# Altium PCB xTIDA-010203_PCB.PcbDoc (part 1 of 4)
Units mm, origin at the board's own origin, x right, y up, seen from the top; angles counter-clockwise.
Board outline 200 x 130 mm, 4 copper layers (Top Layer, Signal Layer 1, Signal Layer 2, Bottom Layer), stack 1.588 mm thick; 249 components, 140 nets, 768 pads, 520 vias.
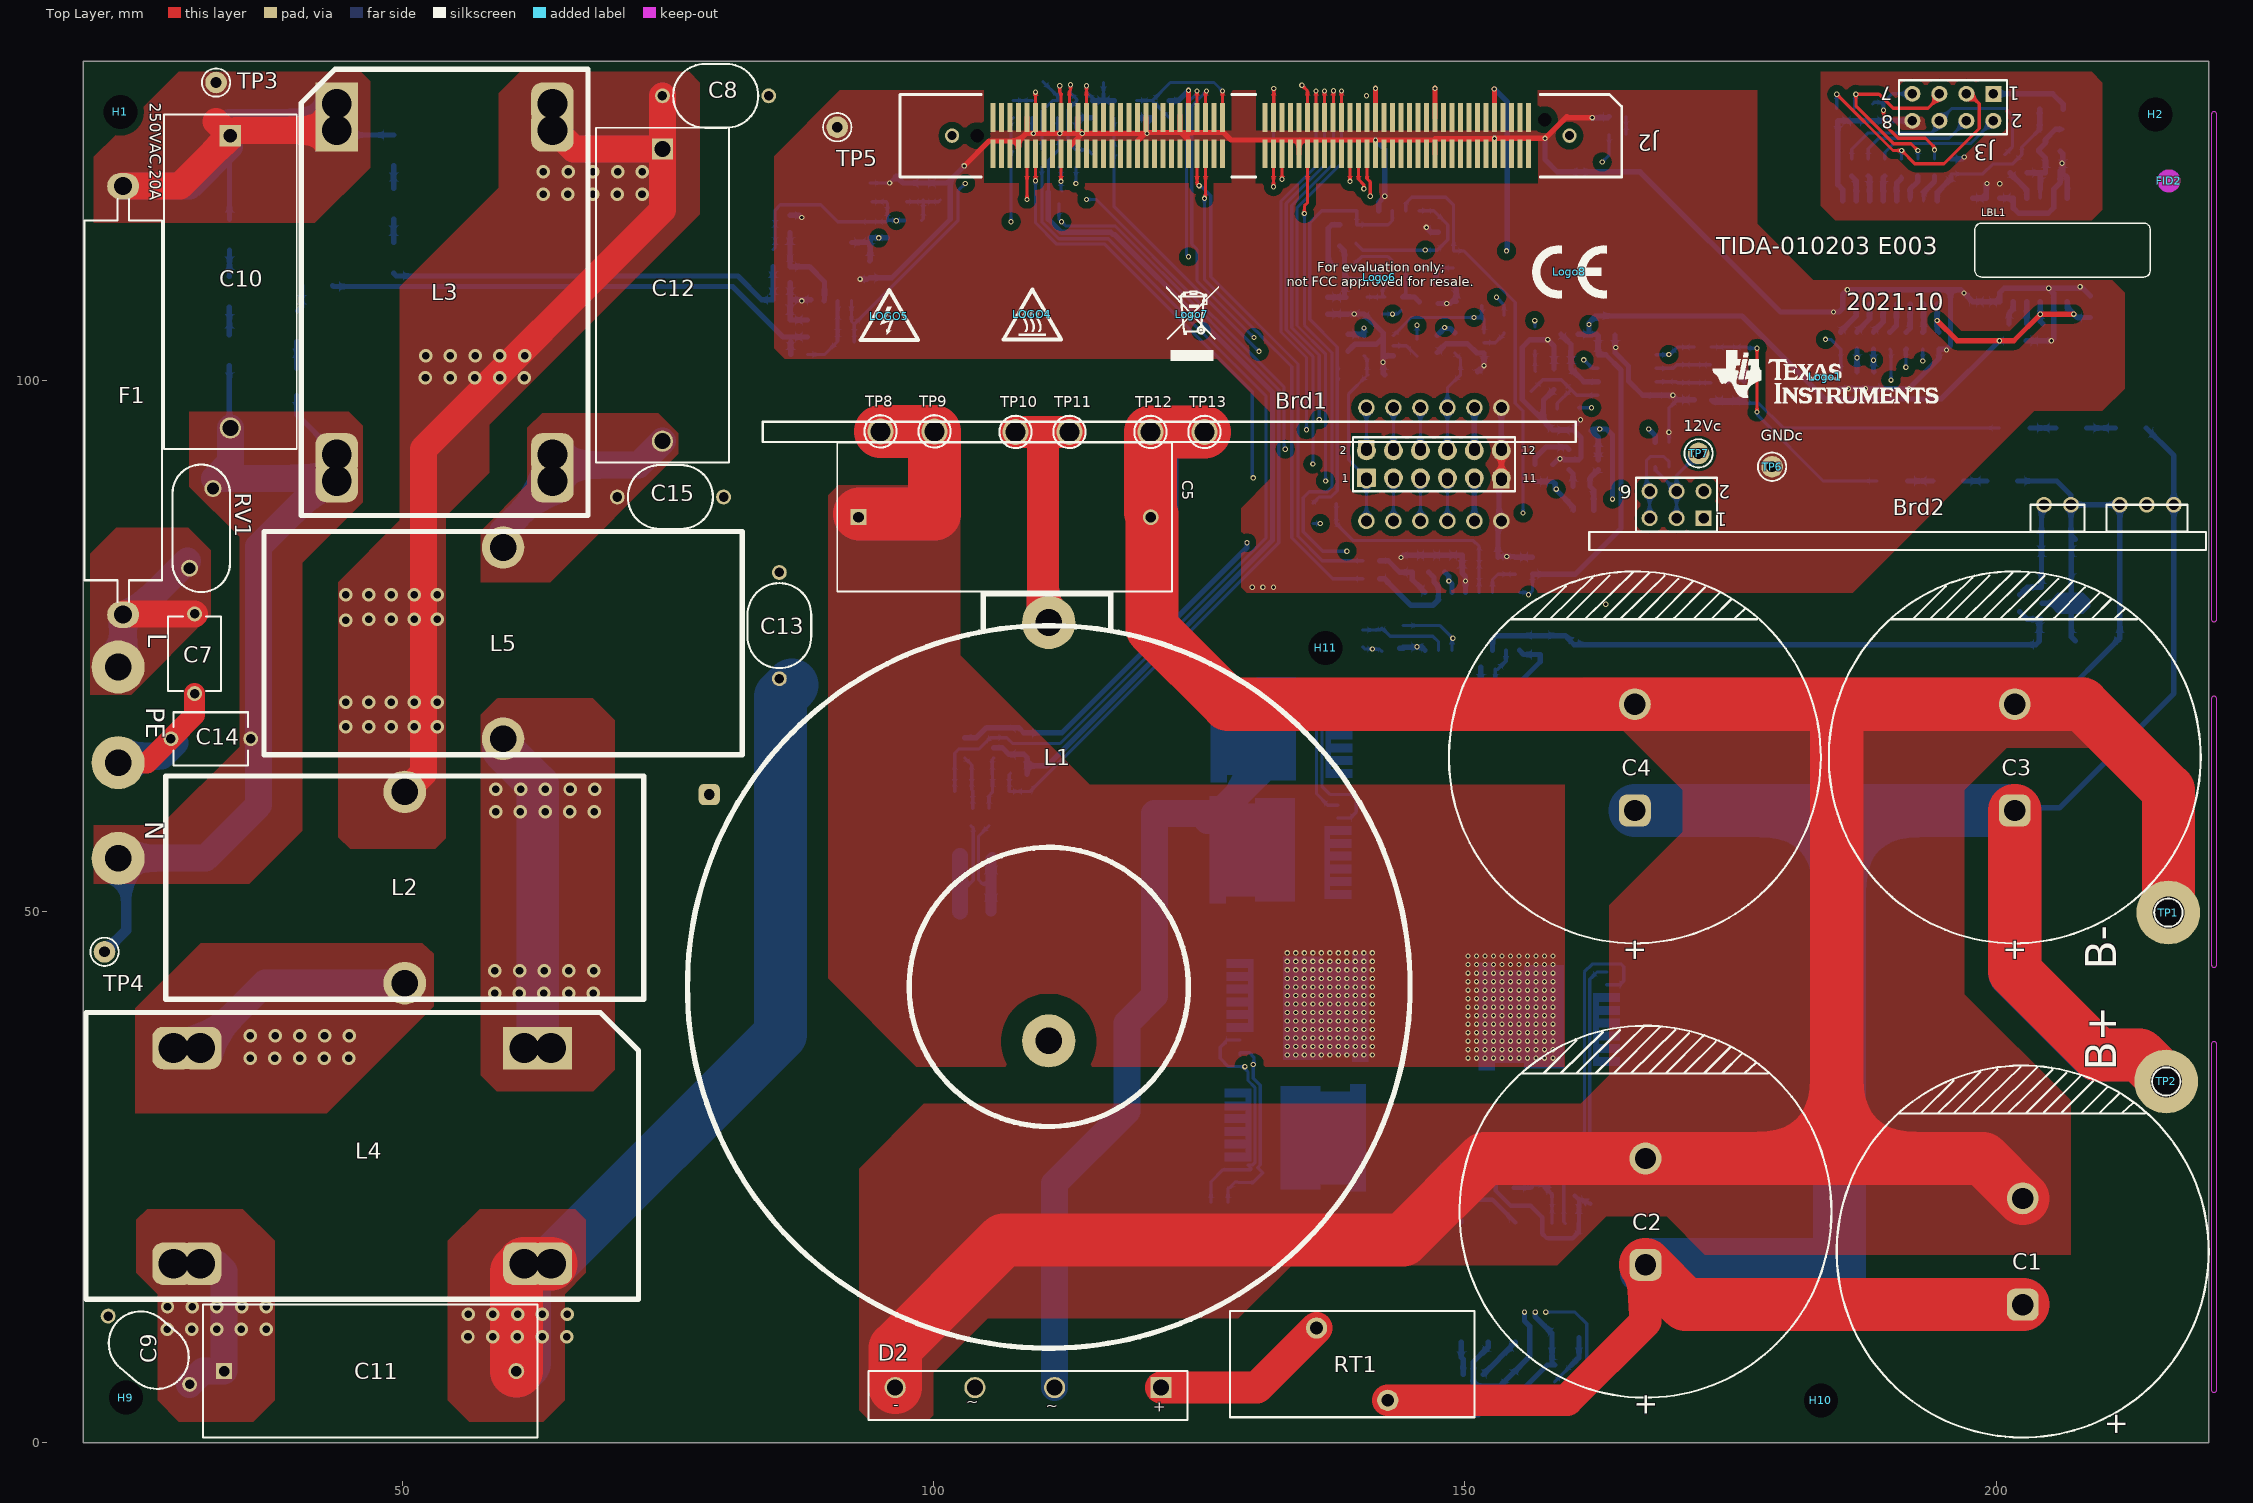
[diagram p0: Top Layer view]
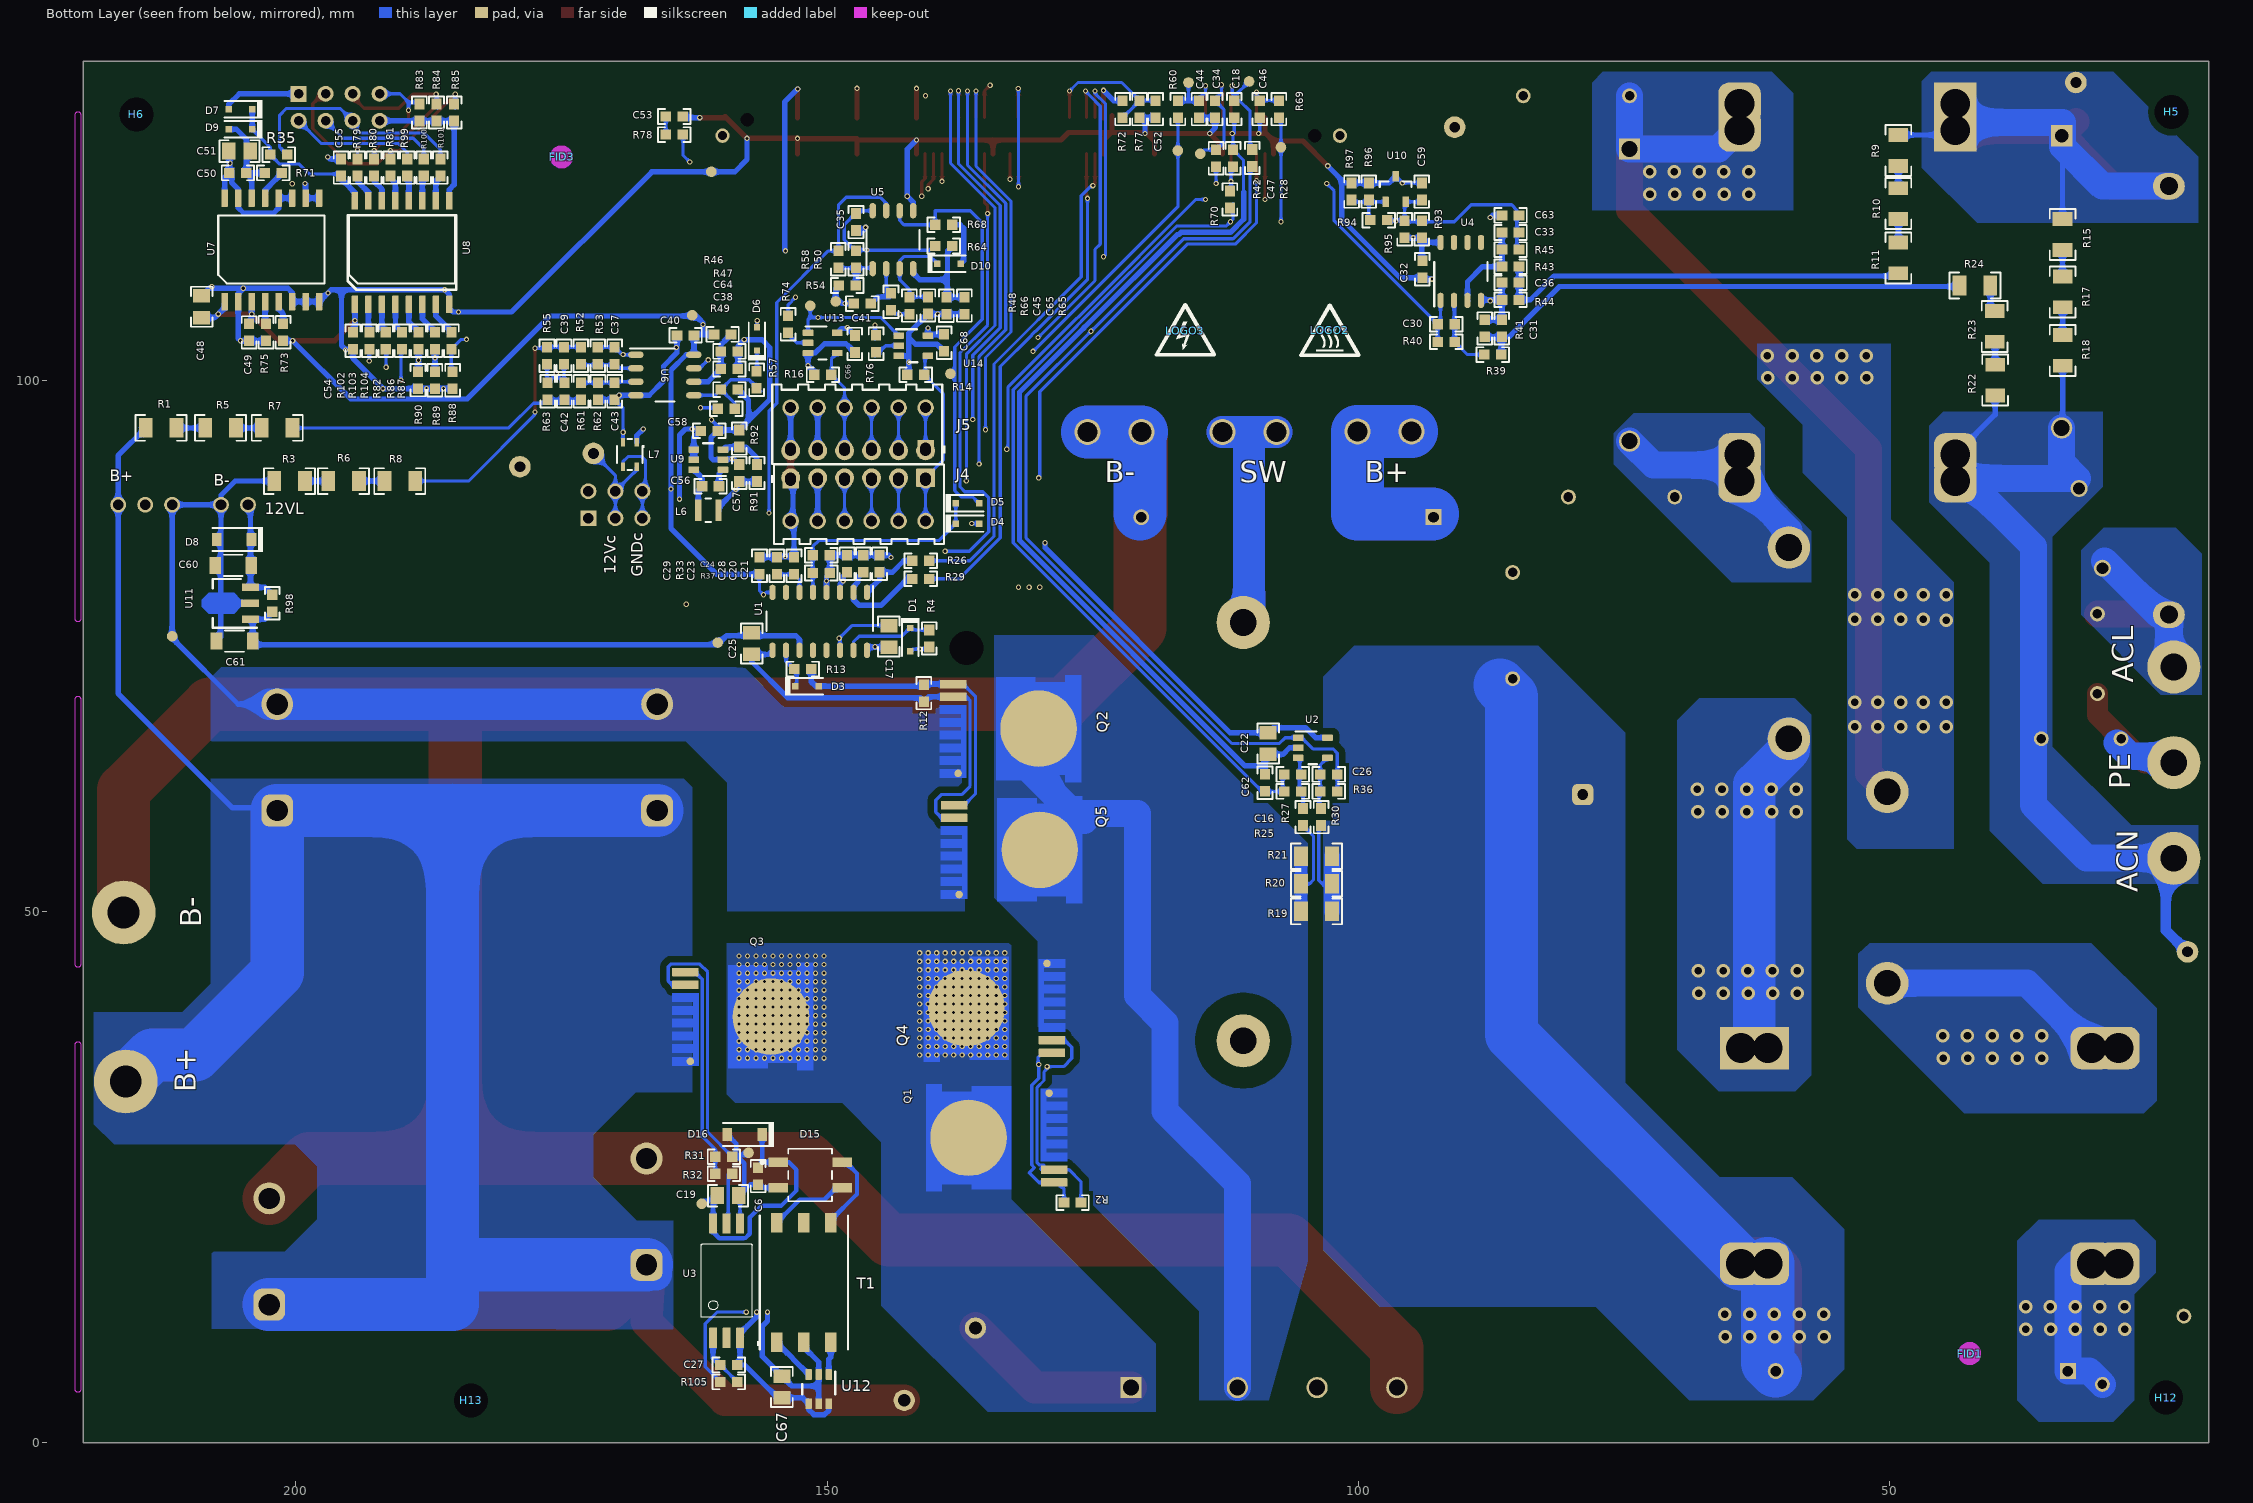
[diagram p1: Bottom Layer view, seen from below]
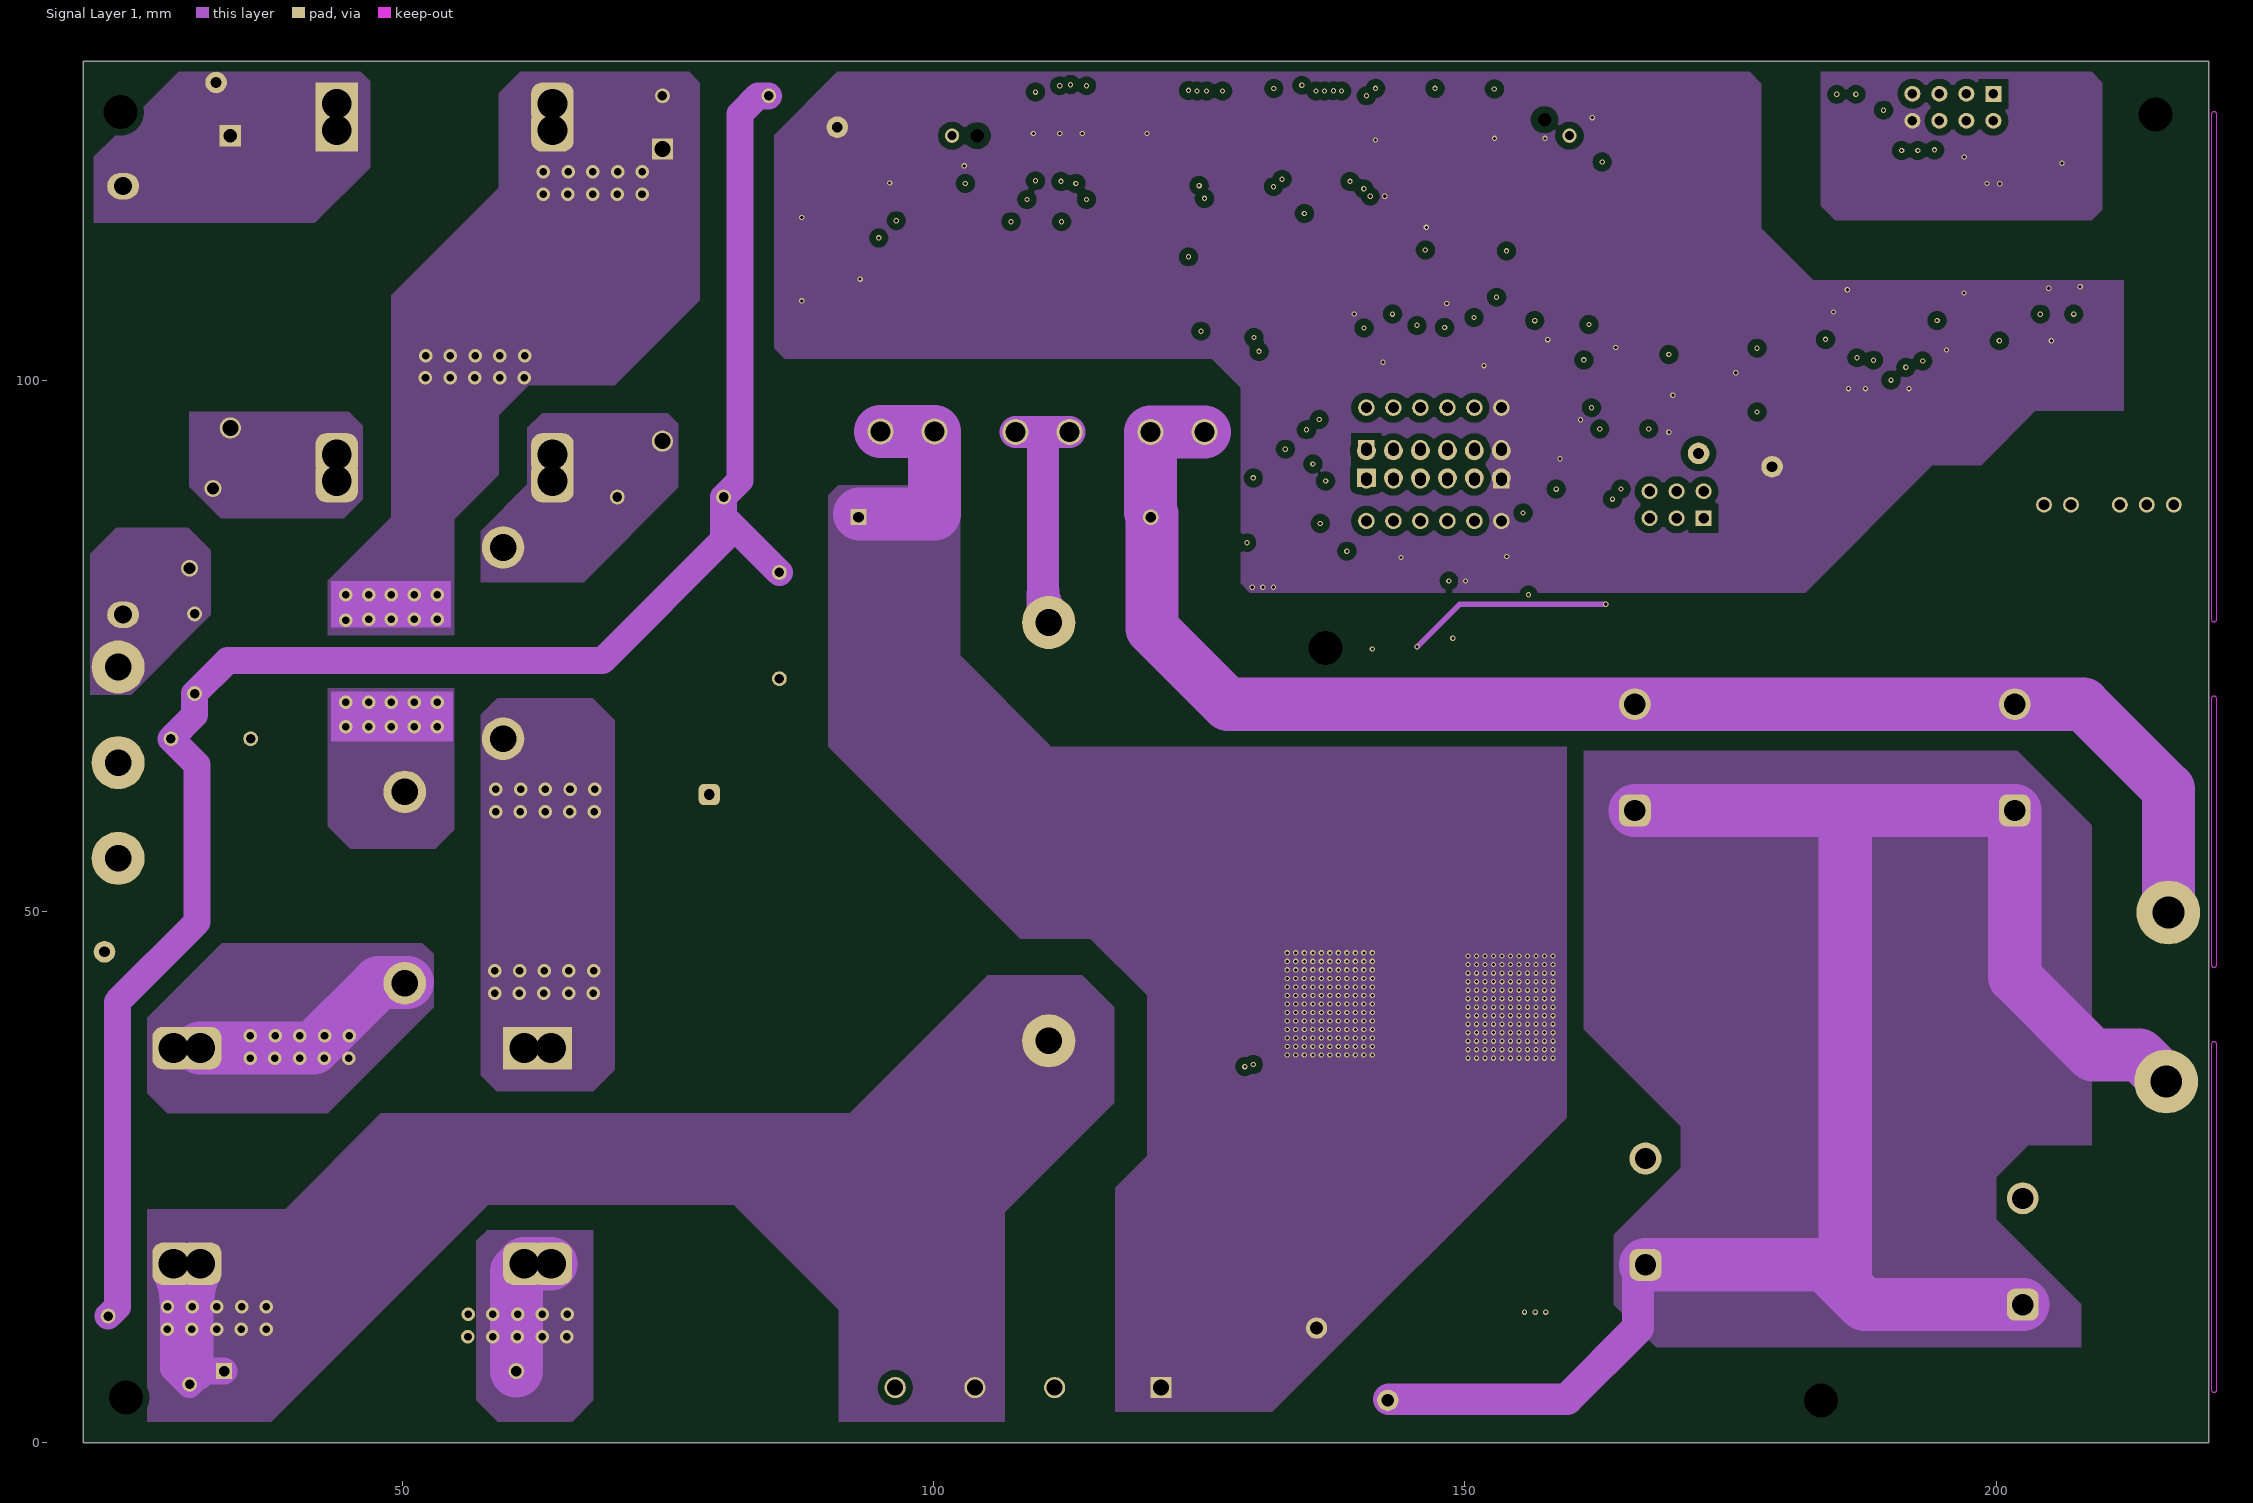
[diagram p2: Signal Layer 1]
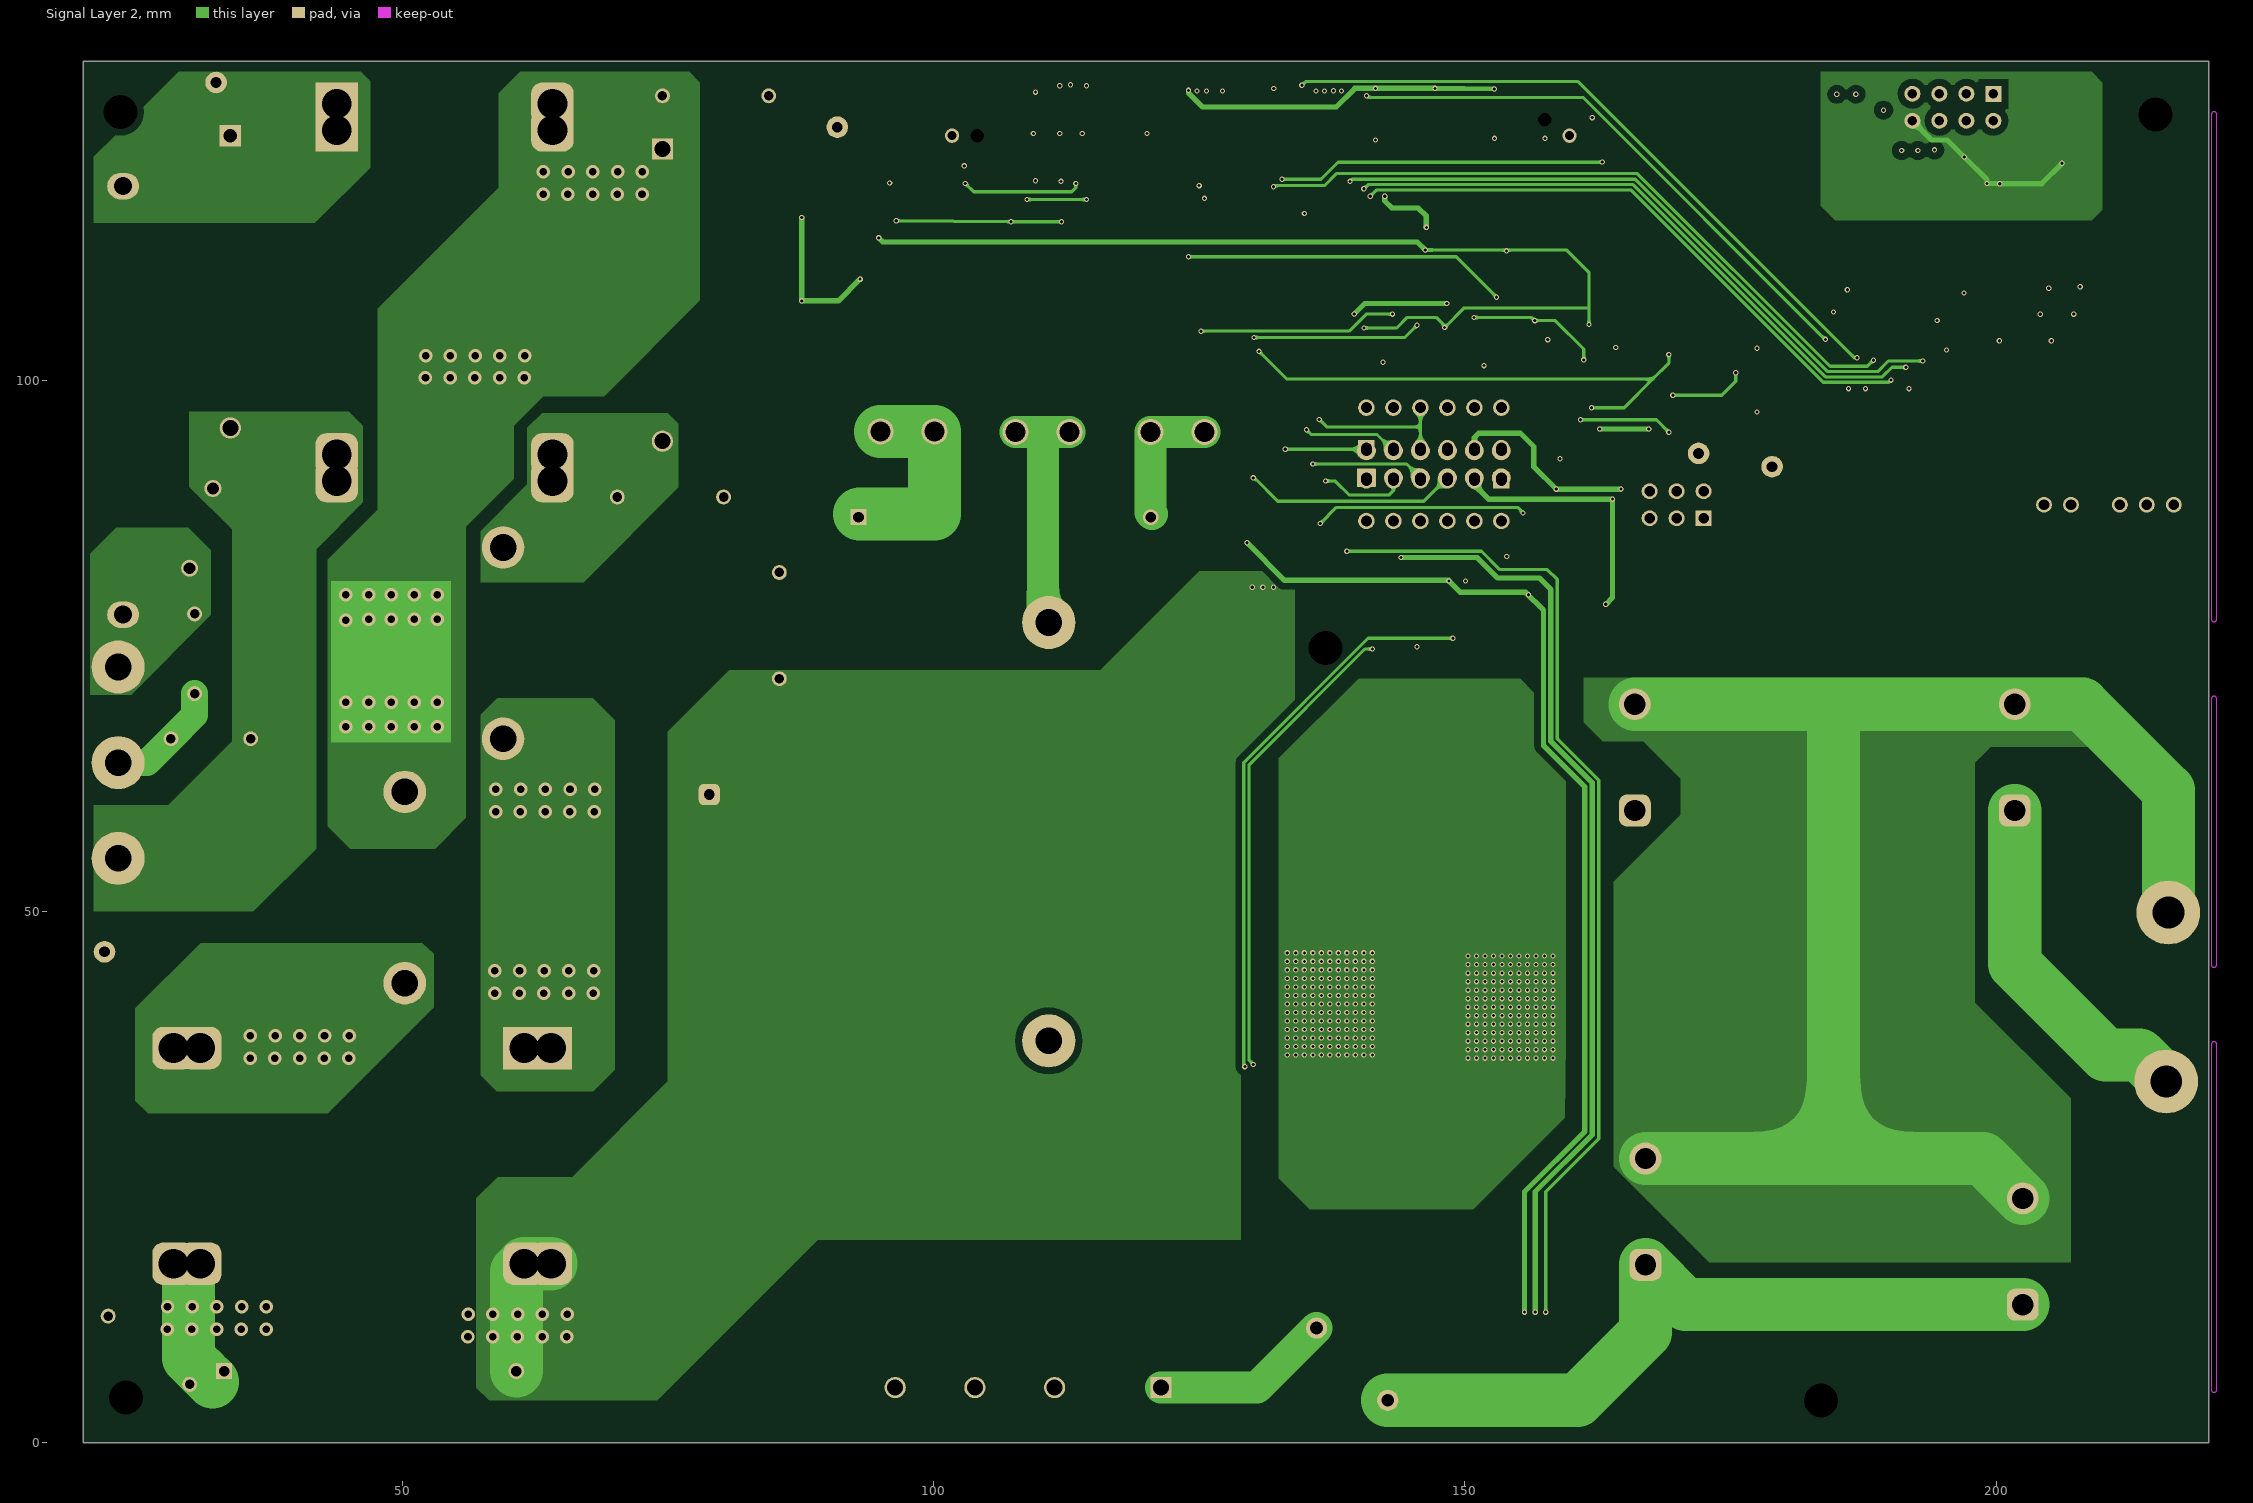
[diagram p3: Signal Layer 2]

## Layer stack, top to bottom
Top Solder: solder mask 0.0102, Solder Resist, Dk 3.5
Top Layer: signal copper 0.07
Dielectric1: prepreg 0.254, FR-4, Dk 4.5
Signal Layer 1: signal copper 0.07
Dielectric 2: core 0.8, FR-4, Dk 4.5
Signal Layer 2: signal copper 0.07
Dielectric 3: prepreg 0.254, FR-4, Dk 4.5
Bottom Layer: signal copper 0.07
Bottom Solder: solder mask 0.0102, Solder Resist, Dk 3.5

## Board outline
20,0 220,0 220,130 20,130
cut-out: 220.25,45 ccw(c220.5,45) 220.75,45 220.75,70 ccw(c220.5,70) 220.25,70
cut-out: 220.25,5 ccw(c220.5,5) 220.75,5 220.75,37.5 ccw(c220.5,37.5) 220.25,37.5
cut-out: 220.25,77.5 ccw(c220.5,77.5) 220.75,77.5 220.75,125 ccw(c220.5,125) 220.25,125

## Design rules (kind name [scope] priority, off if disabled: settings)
AcuteAngle [All] p1: minimum=4.50000000000000E+0001 checktracksonly=FALSE
AssemblyTestPointUsage [All] p1: valid=2
BoardOutlineClearance BoardOutlineClearance_MountingHoles [OnCopper and InComponentClass('Mounting Holes')] p1: gap=1 ignorepadtopadclearanceinfootprint=FALSE
BoardOutlineClearance BoardOutlineClearance_Poly [OnCopper and IsPoly] p2: gap=0.635 ignorepadtopadclearanceinfootprint=FALSE
BoardOutlineClearance [OnCopper and Not InComponentClass('Logo') and not InComponentClass('FiducialMark') and not InRegion(1000,500,4000,800) and not InPoly] p3: gap=0.5 ignorepadtopadclearanceinfootprint=FALSE
Clearance Clearance_Keepouts [((IsTrack Or IsArc) And Not InPoly) And IsFree and IsKeepOut vs ((IsTrack Or IsArc) And Not InPoly) And IsFree and IsKeepOut] p1: gap=0 ignorepadtopadclearanceinfootprint=FALSE
Clearance Clearance_Poly [InPolygon] p2: gap=0.635 ignorepadtopadclearanceinfootprint=TRUE
Clearance Clearance_FiducialMark [IsKeepOut and InComponentClass('FiducialMark') vs IsPad and InComponentClass('FiducialMark')] p3: gap=0 ignorepadtopadclearanceinfootprint=FALSE
Clearance [All] p4: gap=0.2 ignorepadtopadclearanceinfootprint=TRUE
ComponentClearance ComponentClearance_MountingHoles_FiducialMarks [InComponentClass('Mounting Holes') vs InComponentClass('FiducialMark')] p1 off: gap=1.27 collisioncheckmode=3 verticalgap=0.254 showdistances=FALSE
ComponentClearance ComponentClearance_Shunt [InComponentClass('Header') vs InComponentClass('Shunt')] p2 off: gap=0 collisioncheckmode=3 verticalgap=0 showdistances=FALSE
ComponentClearance ComponentClearance_Logo [InComponentClass('Logo')] p3 off: gap=1.27 collisioncheckmode=3 verticalgap=0.254 showdistances=FALSE
ComponentClearance ComponentClearance_ScrewToNut [(HasFootprint('NY PMS 440 0025 PH')) vs (HasFootprint('Keystone_1902C'))] p4 off: gap=0.127 collisioncheckmode=3 verticalgap=0.254 showdistances=FALSE
ComponentClearance ComponentClearance_MountingHoles [InComponentClass('Mounting Holes')] p5 off: gap=6.35 collisioncheckmode=3 verticalgap=2540 showdistances=FALSE
ComponentClearance ComponentClearance_SmallPassives [HasFootprint('0201*') or HasFootprint('0402*') or HasFootprint('0508') or HasFootprint('0603*') or HasFootprint('0612') or HasFootprint('0805*') or HasFootprint('0815*') or HasFootprint('0830*') or HasFootprint('1206*') or HasFootprint('1210*') or HasFootprint('1808*') or HasFootprint('1812*') or HasFootprint('1825*') or HasFootprint('2010*') or HasFootprint('2220*') or HasFootprint('2225*') or HasFootprint('2512*') or HasFootprint('2728*') or HasFootprint('3518*') vs HasFootprint('0201*') or HasFootprint('0402*') or HasFootprint('0508') or HasFootprint('0603*') or HasFootprint('0612') or HasFootprint('0805*') or HasFootprint('0815*') or HasFootprint('0830*') or HasFootprint('1206*') or HasFootprint('1210*') or HasFootprint('1808*') or HasFootprint('1812*') or HasFootprint('1825*') or HasFootprint('2010*') or HasFootprint('2220*') or HasFootprint('2225*') or HasFootprint('2512*') or HasFootprint('2728*') or HasFootprint('3518*')] p6 off: gap=0.38 collisioncheckmode=3 verticalgap=0.254 showdistances=FALSE
ComponentClearance ComponentClearance_THtoSMT [IsThruComponent vs IsSMTComponent] p7 off: gap=1.016 collisioncheckmode=3 verticalgap=0.762 showdistances=FALSE
ComponentClearance ComponentClearance_THtoTH [IsThruComponent vs IsThruComponent] p8 off: gap=0.762 collisioncheckmode=3 verticalgap=0.762 showdistances=FALSE
ComponentClearance [All] p9 off: gap=0.762 collisioncheckmode=3 verticalgap=0.254 showdistances=FALSE
DiffPairsRouting [All] p1: maxlimit=2.54 minlimit=0.254 mostfreqgap=0.254 toplayer_minwidth=0.381 toplayer_maxwidth=0.381 toplayer_prefwidth=0.381 midlayer1_minwidth=0.381 midlayer1_maxwidth=0.381 midlayer1_prefwidth=0.381 midlayer2_minwidth=0.381 midlayer2_maxwidth=0.381 midlayer2_prefwidth=0.381 bottomlayer_minwidth=0.381 bottomlayer_maxwidth=0.381 bottomlayer_prefwidth=0.381 maxuncoupledlength=25.4
FabricationTestPointUsage TestPointUsage [All] p1: valid=2 allowmultiple=FALSE
FabricationTestpoint Testpoint [All] p1: side=3 testpointundercomponent=TRUE minsize=1.016 maxsize=2.54 preferedsize=1.524 minholesize=0 maxholesize=1.016 preferedholesize=0.813 testpointgrid=0.025 allowsidetop=TRUE allowsidebottom=TRUE usegrid=TRUE gridtolerance=0
FanoutControl Fanout_LCC [IsLCC] p1: bgadir=Out bgaviamode=Centered fanoutstyle=Auto fanoutdirection=Alternating viagrid=0.025 // Fanout_LCC (Default Rule)
FanoutControl Fanout_BGA [IsBGA] p2: bgadir=Out bgaviamode=Centered fanoutstyle=Auto fanoutdirection=Alternating viagrid=0.025 // Fanout_BGA (Default Rule)
FanoutControl Fanout_Default [All] p4: bgadir=Out bgaviamode=Centered fanoutstyle=Auto fanoutdirection=Alternating viagrid=0.025 // Fanout_Default (Default Rule)
FanoutControl Fanout_Small [(CompPinCount < 5)] p5: bgadir=Out bgaviamode=Centered fanoutstyle=Auto fanoutdirection=OutThenIn viagrid=0.025 // Fanout_Small (Default Rule)
Height [All] p1 off: minheight=0 maxheight=25.4 prefheight=12.7
HoleSize [All] p1: absolutevalues=TRUE maxlimit=6.375 minlimit=0.2 maxpercent=80.000 minpercent=20.000
HoleToHoleClearance [All] p1: gap=0 allowstackedmicrovias=TRUE
MinimumAnnularRing MinimumAnnularRing_ThermalPadVias [IsVia and InAnyComponent] p1: minimumring=0.15
MinimumAnnularRing [All] p2: minimumring=0.1
MinimumSolderMaskSliver MinimumSolderMaskSliver_Logo [InComponentClass('Logo') vs InComponentClass('Logo')] p1: minsoldermaskwidth=0.018
MinimumSolderMaskSliver [All] p2: minsoldermaskwidth=0.1
PlaneConnect [All] p1: planeconnectstyle=Direct reliefexpansion=0.254 reliefentries=4 reliefconductorwidth=0.254 reliefairgap=0.254
PolygonConnect [All] p1: connectstyle=Direct reliefconductorwidth=0.5 reliefentries=4 polygonreliefangle="90 Angle" airgapwidth=0.254
RoutingVias ThermalPadVias [IsVia and InAnyComponent] p1: holewidth=0.2 width=0.5 viastyle="Through Hole" minholewidth=0.2 minwidth=0.5 maxholewidth=0.33 maxwidth=0.6
RoutingVias [All] p2: holewidth=0.406 width=0.864 viastyle="Through Hole" minholewidth=0.2 minwidth=0.5 maxholewidth=1.016 maxwidth=1.651
SilkToBoardRegionClearance [Not ((IsComment or IsDesignator) And (Hide <> 'False')) and not InRegion(1000,500,4000,800)] p1:
SilkToSilkClearance SilkToSilkClearance_Pb-FreeLogo [(HasFootprint('Pb-Free_Overlay_Medium') OR HasFootprint('Pb-Free_Overlay_Small')) vs (HasFootprint('Pb-Free_Overlay_Medium') OR HasFootprint('Pb-Free_Overlay_Small'))] p1: silktosilkclearance=0
SilkToSilkClearance [All] p2: silktosilkclearance=0.1
SilkToSolderMaskClearance SilkToComponentPadClearance [(IsPad or IsFill or IsRegion) and InAnycomponent] p1 off: minsilkscreentomaskgap=0.127 clearancetoexposedcopper=TRUE
SilkToSolderMaskClearance "Silk to Solder Mask Opening" [All] p2 off: minsilkscreentomaskgap=0.1 clearancetoexposedcopper=FALSE
SolderMaskExpansion [All] p1: expansion=0.05
UnRoutedNet [All] p1: checkbadconnections=TRUE
Width [All] p1: maxlimit=5 minlimit=0.152 preferedwidth=0.254 checkconnectedcopper=TRUE
12 further rules are at their usual default settings.

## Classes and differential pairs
net class INGND: 5Vc GND-c NetT1_1 NetT1_3
component class "xTIDA-010203; CCMTLPFC_AuxP_UCC28740": Brd2 C56 C57 C58 C59 C60 C61 D8 FID1 FID2 FID3 H1 H2 H5 H6 H9 H10 H11 H12 H13 L6 L7 LBL1 Logo1 LOGO2 LOGO3 LOGO4 LOGO5 Logo6 Logo7 Logo8 R91 R92 R93 R94 R95 R96 R97 R98 U9 U10 U11
component class "xTIDA-010203; CCMTLPFC_PowerStage": Brd1 C1 C2 C3 C4 C5 C6 C7 C8 C9 C10 C11 C12 C13 C14 C15 C16 C17 C18 C19 C20 C21 C22 C23 C24 C25 C26 C27 C28 C29 C30 C31 C32 C33 C34 C35 C36 C37 C38 C39 C40 C41 C42 C43 C44 C45 C62 C63 C64 C65 C66 C67 C68 D1 D2 D3 D4 D5 D6 D10 D15 D16 F1 J4 J5 L1 L2 L3 L4 L5 Q1 Q2 Q3 Q4 Q5 R1 R2 R3 R4 R5 R6 R7 R8 R9 R10 R11 R12 R13 R14 R15 R16 R17 R18 R19 R20 R21 R22 R23 R24 R25 R26 R27 R28 R29 R30 R31 R32 R33 R36 R37 R39 R40 R41 R42 R43 R44 R45 R46 R47 R48 R49 R50 R52 R53 R54 R55 R57 R58 R60 R61 R62 R63 R64 R65 R66 R68 R105 RT1 RV1 T1 TP1 TP2 TP3 TP4 TP5 TP6 TP7 TP8 TP9 TP10 TP11 TP12 TP13 U1 U2 U3 U4 U5 U6 U12 U13 U14
net class HV: AC-L B1+ B+ NetC7_1 NetC8_1 NetC10_1 SWNODE1
net class MV: 12V_B- 12V_L +BRDG_P -BRDG_P B- DRV_RELAY GND-RLY ISO_12V_RLY NetD3_2 NetR1_1 NetR3_1 NetR32_1
component class "xTIDA-010203; CCMTLPFC_ControlStage": C46 C47 C48 C49 C50 C51 C52 C53 C54 C55 D7 D9 DC1 J2 J3 R35 R69 R70 R71 R72 R73 R74 R75 R76 R77 R78 R79 R80 R81 R82 R83 R84 R85 R86 R87 R88 R89 R90 R99 R100 R101 R102 R103 R104 U7 U8
component class FiducialMark: FID1 FID2 FID3
component class Label: LBL1
component class Logo: Logo1
component class "Mounting Holes": H1 H2 H9 H10 H11

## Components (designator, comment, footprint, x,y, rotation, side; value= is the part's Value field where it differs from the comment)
Brd1 "LMG3422EVM-043" ? 140.74,92.584 r0 top locked
Brd2 "AUXP60W" AUXP60W 204.5,87 r180 top locked
C1 "450MXK680MEFCSN35X45" "WCAP-AI3H_3500x5700 - H" 202.5,18 r90 top locked value=680uF
C2 "450MXK680MEFCSN35X45" "WCAP-AI3H_3500x5700 - H" 167,21.75 r90 top locked value=680uF
C3 "450MXK680MEFCSN35X45" "WCAP-AI3H_3500x5700 - H" 201.75,64.5 r90 top locked value=680uF
C4 "450MXK680MEFCSN35X45" "WCAP-AI3H_3500x5700 - H" 166,64.5 r90 top locked value=680uF
C5 "ECWFG2J225" B32924_24.5mm 106.7,87.1 r0 top value=2.2uF
C6 "C1608X5R1V475K080AC" 0603#1 156.5,25.1 r270 bottom value=4.7uF
C7 "DE2B3KY331KB3BU02F" KY_700x500x1000 30.476,74.25 r270 top locked value=330pF
C8 "CD45-E2GA152M-NKA" CD45_800x600x1200 79.5,126.75 r0 top value=1500pF
C9 "CD45-E2GA152M-NKA" CD45_800x600x1200 26.17,8.714 r140 top value=1500pF
C10 "890324027012" B32924_21.5mm#1 33.834,109.25 r270 top locked value=1.2uF
C11 "890324027012" B32924_21.5mm#2 47,6.75 r0 top locked value=1.2uF
C12 "890324027012" B32924_21.5mm#3 74.5,108 r270 top locked value=1.2uF
C13 "CD45-E2GA152M-NKA" CD45_800x600x1200 85.5,76.9 r270 top value=1500pF
C14 "DE2B3KY331KB3BU02F" KY_700x500x1000 32,66.25 r0 top value=330pF
C15 "CD45-E2GA152M-NKA" CD45_800x600x1200 75.25,89 r180 top value=1500pF
C16 "CGA3E2C0G1H220J080AA" 0603#1 106.2,62.9 r180 bottom value=22pF
C17 "GRM21BR61E106MA73L" 0805_HV 144.2,75.884 r90 bottom value=10uF
C18 "C0603C472J5RACTU" 0603#1 111.7,125.5 r90 bottom value=4700pF
C19 "GRM21BZ71E106KE15L" 0805_HV 159.337,23.253 r180 bottom value=10uF
C20 "GCJ188R71H102KA01D" 0603#1 146.606,82.72 r90 bottom value=1000pF
C21 "GCJ188R71H102KA01D" 0603#1 145.066,82.72 r270 bottom value=1000pF
C22 "GRM21BR61E106MA73L" 0805_HV 108.5,65.8 r90 bottom value=10uF
C23 "C0603X103K5RACTU" 0603#1 153.121,82.536 r90 bottom value=0.01uF
C24 "GRM188R71E104KA01D" 0603#1 150.547,83.52 r0 bottom value=0.1uF
C25 "GRM21BR61E106MA73L" 0805_HV 157.1,75.2 r270 bottom value=10uF
C26 "CGA3E2C0G1H220J080AA" 0603#1 102.796,62.9 r0 bottom value=22pF
C27 "GCJ188R71H102KA01D" 0603#1 159.253,7.328 r0 bottom value=1000pF
C28 "GRM185R60J105KE26D" 0603#1 148.121,82.72 r90 bottom value=1uF
C29 "C0603X103K5RACTU" 0603#1 156.371,82.536 r90 bottom value=0.01uF
C30 "GRM188R71H102KA01D" 0603#1 91.75,105.251 r0 bottom value=1000pF
C31 "GRM188R71H102KA01D" 0603#1 86.515,104.862 r90 bottom value=1000pF
C32 "GRM188R71E104KA01D" 0603#1 94,110.425 r90 bottom value=0.1uF
C33 "GRM188R71H102KA01D" 0603#1 85.7,113.89 r180 bottom value=1000pF
C34 "GRM188R71E104KA01D" 0603#1 113.5,125.5 r90 bottom value=0.1uF
C35 "GRM188R71E104KA01D" 0603#1 147.286,114.872 r90 bottom value=0.1uF
C36 "GRM188R71H102KA01D" 0603#1 85.7,109.166 r0 bottom value=1000pF
C37 "GRM188R71H102KA01D" 0603#1 170,102.301 r90 bottom value=1000pF
C38 "GRM188R71H471KA01D" 0603#1 159.2,99.11 r180 bottom value=470pF
C39 "GRM188R71H102KA01D" 0603#1 174.774,102.301 r270 bottom value=1000pF
C40 "GRM188R71E104KA01D" 0603#1 163.329,104.212 r180 bottom value=0.1uF
C41 "NC" 0603#2 146.707,107.2 r180 bottom value=0.1uF
C42 "GRM188R71H102KA01D" 0603#1 174.726,98.949 r90 bottom value=1000pF
C43 "GRM188R71H102KA01D" 0603#1 170,98.949 r90 bottom value=1000pF
C44 "GRM188R61E474KA12D" 0603#1 115,125.5 r90 bottom value=0.47uF
C45 "NC" 0603#2 140.522,107.02 r270 bottom value=0.1uF
C46 "GRM188R71E104KA01D" 0603#1 109.3,125.5 r90 bottom value=0.1uF
C47 "GRM188R71E104KA01D" 0603#1 111.8,120.864 r270 bottom value=0.1uF
C48 "GRM21BR61E106MA73L" 0805_HV 208.866,106.9 r90 bottom value=10uF
C49 "GRM188R71E104KA01D" 0603#1 204.4,104.489 r90 bottom value=0.1uF
C50 "GRM188R71E104KA01D" 0603#1 205.45,119.5 r0 bottom value=0.1uF
C51 "GRM21BR61E106MA73L" 0805_HV 205.298,121.55 r180 bottom value=10uF
C52 "GRM188R71H103KA01D" 0603#1 119.1,125.5 r270 bottom value=0.01uF
C53 "GRM188R71H103KA01D" 0603#1 164.38,124.8 r180 bottom value=0.01uF
C54 "C1608X7R1E105K080AB" 0603#2 194.625,103.701 r270 bottom value=1uF
C55 "C1608X7R1E105K080AB" 0603#1 195.745,120 r270 bottom value=1uF
C56 "C1608X7R1E104K080AA" 0603#1 160.979,90.012 r180 bottom value=0.1uF
C57 "C1608X5R1A226M080AC" 0603#1 158.27,91.262 r90 bottom value=22uF
C58 "GRM188R61E475KE11D" 0603#1 161.104,95.229 r180 bottom value=4.7uF
C59 "GRM185R60J105KE26D" 0603#1 94.047,117.745 r90 bottom value=1uF
C60 "C3216X5R1E336M160AC" 1206_180 205.891,82.56 r0 bottom value=33uF
C61 "C3216X5R1E336M160AC" 1206_180 205.766,75.445 r0 bottom value=33uF
C62 "C1608X5R1A226M080AC" 0603#1 108.8,62.1 r90 bottom value=22uF
C63 "C1608X5R1A226M080AC" 0603#1 85.7,115.5 r0 bottom value=22uF
C64 "GRM188R71E104KA01D" 0603#2 159.2,101.046 r180 bottom value=0.1uF
C65 "GRM188R71E104KA01D" 0603#2 138.786,106.998 r90 bottom value=0.1uF
C66 "GRM188R71E104KA01D" 0603#2 147.4,103.399 r90 bottom value=0.1uF
C67 "GCM21BR71C475KA73L" 0805_HV 154.253,5.253 r270 bottom value=4.7uF
C68 "GRM188R71E104KA01D" 0603#2 139,103.52 r90 bottom value=0.1uF
D1 "BAS316" sod-323 142.197,75.577 r270 bottom value=100V
D2 "D25XB60-7000" 5S 108.9,5.2 r180 top value=600V
D3 "BAS316" sod-323 151.9,71.2 r180 bottom value=100V
D4 "BAS316" sod-323 136.8,86.5 r180 bottom value=100V
D5 "BAS316" sod-323 136.8,88.4 r180 bottom value=100V
D6 "BAS316" sod-323 156.608,103.889 r90 bottom value=100V
D7 "BAS316" sod-323 205.2,125.5 r0 bottom value=100V
D8 "CRZ18" SOD-123 205.816,85 r0 bottom value=18V
D9 "BAS316" sod-323 205.2,123.601 r0 bottom value=100V
D10 "BAS316" sod-323 138.526,110.948 r180 bottom value=100V
D15 "KMB23STR" FP-KMB23STR_SMT_4MM725_3MM85-MFG 151.6,25.2 r180 bottom
D16 "BZT52C16-7-F" SOD-123 157.758,29 r0 bottom value=16V
F1 "0325020.MXP" FUSE_0325 23.75,98.09 r270 top locked
FID1 "Fiducial" Fiducial10-20 42.5,8.4 r180 bottom
FID2 "Fiducial" Fiducial10-20 216.25,118.75 r0 top
FID3 "Fiducial" Fiducial10-20 175,121 r180 bottom
H1 "NY PMS 440 0025 PH" "NY PMS 440 0025 PH" 23.5,125.25 r0 top locked
H2 "NY PMS 440 0025 PH" "NY PMS 440 0025 PH" 215,125 r0 top locked
H5 "1902C" Keystone_1902C 23.5,125.25 r180 bottom locked
H6 "1902C" Keystone_1902C 215,125 r180 bottom locked
H9 "NY PMS 440 0025 PH" "NY PMS 440 0025 PH" 24,4.25 r0 top locked
H10 "NY PMS 440 0025 PH" "NY PMS 440 0025 PH" 183.5,4 r0 top locked
H11 "NY PMS 440 0025 PH" "NY PMS 440 0025 PH" 136.893,74.8 r0 top locked
H12 "1902C" Keystone_1902C 24,4.25 r180 bottom locked
H13 "1902C" Keystone_1902C 183.5,4 r180 bottom locked
J2 "HSEC8-160-01-L-DV-A-BL" controlCARD-120HSEC 128.957,122.978 r0 top locked
J3 "Header 4X2" HDR2X4 199.74,126.94 r180 top locked
J4 "0448120024" Molex_0448120024 147.09,88.651 r180 bottom locked
J5 "0448120024" Molex_0448120024 147.09,95.501 r0 bottom locked
L1 "ARLDC807842C201N1B" ARLDC807842C201N1B 110.85,42.9 r270 top locked value=300uH
L2 "ARLDC472145C500N1B" ARLDC472145C500N1B 50.25,52.25 r180 top locked
L3 "ARCDC422740E102N2B" "ARCDC422740E102 N2B" 54,108.25 r0 top locked value=1mH
L4 "ARCDC522747E152N2B" ARCDC522747E152N2B 46.25,27 r270 top locked value=1.6mH
L5 "ARLDC472145C500N1B" ARLDC472145C500N1B 59.5,75.25 r180 top locked
L6 "74438323100" VLS252010HBX 161.179,87.762 r180 bottom value=10uH
L7 "ACM2520-601-2P-T002" TDK_ACM2520-2P 168.572,93 r270 bottom
LBL1 "THT-14-423-10" Label_650x200 206.25,112.235 r0 top
Logo1 "Texas Instruments" TI_Stacked_Overlay_Small 183.934,100.298 r0 top
LOGO2 "CAUTION HOT SURFACE" IEC_HotSurface_Small 102.7,104.7 r180 bottom
LOGO3 "DANGER HIGH VOLTAGE" IEC_HighVoltage_Small 116.3,104.621 r180 bottom
LOGO4 "CAUTION HOT SURFACE" IEC_HotSurface_Small 109.309,106.179 r0 top
LOGO5 "DANGER HIGH VOLTAGE" IEC_HighVoltage_Small 95.849,106 r0 top
Logo6 "FCC disclaimer" FCC_disclaimer_stacked 141.945,109.7 r0 top
Logo7 "WEEE logo" WEEE_Minimum 124.31,106.179 r0 top
Logo8 "CE Mark" CE_Mark_5mm 159.85,110.173 r0 top
Q1 "IPT60R035CFD7XTMA1" FP-IPT60R080G7XTMA1_HSOF-8-MFG 134,28.7 r90 bottom
Q2 "IPT60R035CFD7XTMA1" FP-IPT60R080G7XTMA1_HSOF-8-MFG 132.8,67.2 r270 bottom
Q3 "IPT60R022S7XTMA1" FP-IPT60R080G7XTMA1_HSOF-8-MFG 158,40.1 r270 bottom
Q4 "IPT60R035CFD7XTMA1" FP-IPT60R080G7XTMA1_HSOF-8-MFG 134.2,40.9 r90 bottom
Q5 "IPT60R035CFD7XTMA1" FP-IPT60R080G7XTMA1_HSOF-8-MFG 132.7,55.8 r270 bottom
R1 "RCV12061M00FKEA" 1206 212.672,95.5 r0 bottom value=1.00Meg
R2 "RC0603FR-07100KL" 0603#1 126.913,22.6 r0 bottom value=100k
R3 "RCV12061M00FKEA" 1206 200.58,90.5 r0 bottom value=1.00Meg
R4 "100R 0603" 0603#1 140.4,75.69 r270 bottom value=100R
R5 "RCV12061M00FKEA" 1206 207.081,95.5 r0 bottom value=1.00Meg
R6 "RCV12061M00FKEA" 1206 195.5,90.5 r0 bottom value=1.00Meg
R7 "RCV12061M00FKEA" 1206 201.75,95.5 r0 bottom value=1.00Meg
R8 "RCV12061M00FKEA" 1206 190.22,90.5 r0 bottom value=1.00Meg
R9 "RCV12061M00FKEA" 1206 49.2,121.61 r270 bottom value=1.00Meg
R10 "RCV12061M00FKEA" 1206 49.2,116.6 r270 bottom value=1.00Meg
R11 "RCV12061M00FKEA" 1206 49.2,111.5 r270 bottom value=1.00Meg
R12 "RC0603FR-07100KL" 0603#1 140.9,70.548 r90 bottom value=100k
R13 "100R 0603" 0603#1 152.3,72.8 r180 bottom value=100R
R14 "ERJ-3EKF1002V" 0603#1 141.664,100.499 r0 bottom value=10.0k
R15 "RV1206FR-07330KL" 1206 33.752,113.7 r90 bottom value=330k
R16 "ERJ-3EKF1002V" 0603#1 150.4,100.499 r0 bottom value=10.0k
R17 "RV1206FR-07330KL" 1206 33.75,108.3 r90 bottom value=330k
R18 "RV1206FR-07330KL" 1206 33.75,102.8 r90 bottom value=330k
R19 "WSLP1206R0100FEA" 1206 103.962,50.004 r0 bottom value=0.01
R20 "WSLP1206R0100FEA" 1206 103.962,52.602 r0 bottom value=0.01
R21 "WSLP1206R0100FEA" 1206 103.962,55.2 r0 bottom value=0.01
R22 "RCV12061M00FKEA" 1206 40.1,100 r90 bottom value=1.00Meg
R23 "RCV12061M00FKEA" 1206 40.15,105.05 r90 bottom value=1.00Meg
R24 "RCV12061M00FKEA" 1206 42,108.9 r0 bottom value=1.00Meg
R25 "CRCW060310K0FKEA" 0603#1 106.2,61.3 r0 bottom value=10.0k
R26 "ERJ-3EKF1001V" 0603#1 141.2,83 r180 bottom value=1.00k
R27 "ERJ-3EKF1001V" 0603#1 105.226,58.884 r270 bottom value=1.00k
R28 "CRCW060350R0FKEA" 0603#1 110,120.9 r90 bottom value=50
R29 "ERJ-3EKF1001V" 0603#1 141.2,81.3 r180 bottom value=1.00k
R30 "ERJ-3EKF1001V" 0603#1 103.526,58.884 r270 bottom value=1.00k
R31 "ERJ-3EKF1002V" 0603#1 159.719,26.916 r0 bottom value=10.0k
R32 "RC0603FR-0751R1L" 0603#1 159.719,25.316 r0 bottom value=51.1
R33 "CRCW060388K7FKEA" 0603#1 154.737,82.536 r90 bottom value=88.7k
R35 "RC0603FR-079K31L" 0603#1 201.615,121.217 r180 bottom value=9.31k
R36 "CRCW060310K0FKEA" 0603#1 102.796,61.302 r0 bottom value=10.0k
R37 "RC0603FR-0751K1L" 0603#1 150.547,81.845 r0 bottom value=51.1k
R39 "CRCW060310K0FKEA" 0603#1 87.364,102.4 r0 bottom value=10.0k
R40 "ERJ-3EKF2202V" 0603#1 91.75,103.6 r180 bottom value=22.0k
R41 "CRCW060310K0FKEA" 0603#1 88.125,104.862 r270 bottom value=10.0k
R42 "ERJ-3EKF1001V" 0603#1 113.4,120.864 r270 bottom value=1.00k
R43 "CRCW060310K0FKEA" 0603#1 85.7,110.674 r0 bottom value=10.0k
R44 "CRCW060310K0FKEA" 0603#1 85.7,107.556 r180 bottom value=10.0k
R45 "ERJ-3EKF2202V" 0603#1 85.7,112.283 r180 bottom value=22.0k
R46 "RC0603FR-074K3L" 0603#1 159.85,104.3 r0 bottom value=4.30k
R47 "ERJ-3EKF7501V" 0603#1 159.2,102.7 r180 bottom value=7.50k
R48 "ERJ-3EKF1001V" 0603#1 144,107.375 r270 bottom value=1.00k
R49 "CRCW060321K5FKEA" 0603#1 159.5,97.3 r0 bottom value=21.5k
R50 "100k" 0603#1 147.286,111.372 r270 bottom
R52 "CRCW06031K00FKEA" 0603#1 173.183,102.301 r90 bottom value=1.00k
R53 "RC0603FR-0743KL" 0603#1 171.591,102.301 r90 bottom value=43.0k
R54 "ERJ-3EKF1001V" 0603#1 148.1,108.9 r0 bottom value=1.00k
R55 "CRCW06031K00FKEA" 0603#1 176.363,102.301 r270 bottom value=1.00k
R57 "RC0603FR-07430KL" 0603#1 156.647,100.036 r270 bottom value=430k
R58 "2.2k" 0603#1 148.949,111.359 r90 bottom
R60 "ERJ-3EKF1001V" 0603#1 117,125.5 r270 bottom value=1.00k
R61 "CRCW06031K00FKEA" 0603#1 173.151,98.949 r90 bottom value=1.00k
R62 "RC0603FR-0743KL" 0603#1 171.575,98.949 r90 bottom value=43.0k
R63 "CRCW06031K00FKEA" 0603#1 176.303,98.949 r270 bottom value=1.00k
R64 "ERJ-3EKF1002V" 0603#1 139.036,112.622 r0 bottom value=10.0k
R65 "RC0603FR-0720KL" 0603#1 137.086,107.009 r270 bottom value=20.0k
R66 "ERJ-3EKF1001V" 0603#1 142.261,107.009 r270 bottom value=1.00k
R68 "2.2k" 0603#1 139.031,114.622 r0 bottom
R69 "CRCW060310K0FKEA" 0603#1 107.5,125.5 r270 bottom value=10.0k
R70 "CRCW060310K0FKEA" 0603#1 112.1,116.996 r90 bottom value=10.0k
R71 "0R 0603" 0603#1 202.135,119.5 r180 bottom value=0
R72 "RC0603FR-075K1L" 0603#1 122.2,125.5 r90 bottom value=5.10k
R73 "100k 0603" 0603#1 201.2,104.501 r270 bottom value=100k
R74 "100R 0603" 0603#1 153.678,105.268 r90 bottom value=100R
R75 "100R 0603" 0603#1 202.8,104.501 r90 bottom value=100R
R76 "100R 0603" 0603#1 145.4,103.418 r90 bottom value=100R
R77 "RC0603FR-079K31L" 0603#1 120.6,125.5 r90 bottom value=9.31k
R78 "ERJ-3EKF1001V" 0603#1 164.38,123.1 r180 bottom value=1.00k
R79 "RC0603FR-075K1L" 0603#1 194.188,120 r270 bottom value=5.10k
R80 "RC0603FR-075K1L" 0603#1 192.632,120 r270 bottom value=5.10k
R81 "RC0603FR-075K1L" 0603#1 191.075,120 r270 bottom value=5.10k
R82 "RC0603FR-075K1L" 0603#1 188.453,103.701 r270 bottom value=5.10k
R83 "RC0603FR-079K31L" 0603#1 188.375,125.18 r90 bottom value=9.31k
R84 "RC0603FR-079K31L" 0603#1 186.762,125.18 r90 bottom value=9.31k
R85 "RC0603FR-079K31L" 0603#1 185.1,125.18 r90 bottom value=9.31k
R86 "RC0603FR-075K1L" 0603#1 186.91,103.701 r270 bottom value=5.10k
R87 "RC0603FR-075K1L" 0603#1 185.367,103.701 r270 bottom value=5.10k
R88 "RC0603FR-079K31L" 0603#1 185.25,99.974 r90 bottom value=9.31k
R89 "RC0603FR-079K31L" 0603#1 186.91,99.989 r90 bottom value=9.31k
R90 "RC0603FR-079K31L" 0603#1 188.5,100 r90 bottom value=9.31k
R91 "CRCW060388K7FKEA" 0603#1 156.608,91.262 r270 bottom value=88.7k
R92 "CRCW060322K1FKEA" 0603#1 158.27,94.5 r270 bottom value=22.1k
R93 "ERJ-3EKF1001V" 0603#1 94.047,114.183 r90 bottom value=1.00k
R94 "ERJ-3EKF1001V" 0603#1 98.1,115.047 r180 bottom value=1.00k
R95 "ERJ-3EKF1001V" 0603#1 95.664,114.183 r90 bottom value=1.00k
R96 "RC0603FR-078K45L" 0603#1 99.034,117.745 r270 bottom value=8.45k
R97 "RC0603FR-074K7L" 0603#1 100.658,117.745 r270 bottom value=4.70k
R98 "RC0603JR-070RL" 0603#1 202.216,79 r270 bottom value=0
R99 "100R 0603" 0603#2 189.518,120 r90 bottom value=100R
R100 "100R 0603" 0603#2 187.962,120 r90 bottom value=100R
R101 "100R 0603" 0603#2 186.405,120 r90 bottom value=100R
R102 "100R 0603" 0603#2 193.083,103.701 r90 bottom value=100R
R103 "100R 0603" 0603#2 191.54,103.701 r90 bottom value=100R
R104 "100R 0603" 0603#2 189.997,103.701 r90 bottom value=100R
R105 "100R 0603" 0603#1 159.25,5.728 r0 bottom value=100R
RT1 "MS22 50004" MS2250004 139.4,7.4 r180 top value=50
RV1 "S10K275E2" VAR_S10K275E2 31.1,86.05 r270 top
T1 "750315371" Wurth_750315371 152.2,15.1 r90 bottom value=105uH
TP1 "5001" Keystone5001 216.2,49.9 r90 top
TP2 "5000" Keystone5000#1 216,34 r90 top
TP3 "5000" Keystone5000#2 32.5,128 r90 top
TP4 "5004" Keystone5004 22,46.2 r90 top
TP5 "5004" Keystone5004 90.95,123.8 r90 top
TP6 "GNDc" Keystone5004 178.916,91.85 r90 top
TP7 "12Vc" Keystone5004 172,93.1 r90 top
TP8 "Suggest using a net name here" Mill-Max_0312-0-15-15-34-27-10-0 95.02,95.175 r0 top
TP9 "Suggest using a net name here" Mill-Max_0312-0-15-15-34-27-10-0 100.1,95.175 r0 top
TP10 "Suggest using a net name here" Mill-Max_0312-0-15-15-34-27-10-0 107.72,95.124 r0 top
TP11 "Suggest using a net name here" Mill-Max_0312-0-15-15-34-27-10-0 112.8,95.124 r0 top
TP12 "Suggest using a net name here" Mill-Max_0312-0-15-15-34-27-10-0 120.42,95.124 r0 top
TP13 "Suggest using a net name here" Mill-Max_0312-0-15-15-34-27-10-0 125.5,95.124 r0 top
U1 "UCC21222AD" D0016A_N 150.7,77.3 r270 bottom
U2 "OPA607IDBVR" DBV0005A_N 104.3,65.4 r180 bottom
U3 "UCC23511BDWY" DWY0006A 159.466,15.253 r90 bottom
U4 "LM358B" D0008A_N 90.38,110.225 r90 bottom
U5 "TLV3502AID" D0008A_N 143.812,113.213 r90 bottom
U6 "LM358AM" D0008A_N 165.272,100.477 r180 bottom
U7 "UCC12050DVER" DVE0016A 202.25,112.25 r90 bottom
U8 "ISO7763DWR" DW0016B_HV 190,112 r90 bottom
U9 "TPS560430XDBVR" DBV0006A_N 161.179,92.512 r0 bottom
U10 "TLV431BQDBZT" DBZ0003A_N 96.505,117.976 r90 bottom
U11 "UA78L12ACPK" PK0003A_M 204.291,79 r0 bottom
U12 "SN6505BDBVR" DBV0006A_N 150.797,5.053 r270 bottom
U13 "SN74LV1T125DBVR" DBV0005A_N 150.425,103.499 r180 bottom
U14 "SN74LV1T125DBVR" DBV0005A_N 141.897,103.235 r180 bottom

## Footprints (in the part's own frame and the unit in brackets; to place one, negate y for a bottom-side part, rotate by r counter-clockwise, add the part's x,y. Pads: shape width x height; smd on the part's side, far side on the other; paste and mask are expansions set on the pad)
5S [mm] "TH, 4-Leads, Body 4.6x30mm"
  rect 2x2 hole 1.5: 1(-12.5,0)
  round 2 hole 1.5: 2(-2.5,0) 3(5,0) 4(12.5,0)
  silkscreen extent -15,-1.55 15,3.05, body extent -15,-1.55 15,3.05, height 24
0603#1 [mm] "0603 from SM-752 data"
  rect 1x0.95 smd: 1(-0.8,0) 2(0.8,0)
  silkscreen extent -1.52,-0.69 1.52,0.69, body extent -0.87,-0.47 0.87,0.47, height 1
0603#2 [mm] "0603 from SM-752 data"
  rect 1x0.95 smd: 1(0.8,0) 2(-0.8,0)
  silkscreen extent -1.52,-0.69 1.52,0.69, body extent -0.87,-0.47 0.87,0.47, height 1
0805_HV [mil] "0805 with 30mil clearance between pads"
  rect 50x63 smd: 1(-40,0) 2(40,0)
  silkscreen extent -74,-40 74,40, body extent -43,-29 43,29, height 57
1206 [mm] "1206 from SM-752 data"
  rect 1.3x1.85 smd: 1(-1.45,0) 2(1.45,0)
  silkscreen extent -2.4,-1.21 2.4,1.21, body extent -1.7,-0.9 1.7,0.9, height 1.35
1206_180 [mm] "1206_180"
  rect 1.1x1.6 smd: 1(-1.7,0) 2(1.7,0)
  silkscreen extent -0.9,-1 0.9,1, body extent -1.75,-0.95 1.75,0.95, height 1.8
"ARCDC422740E102 N2B" [mm] "CM CHOKE 1mH, D2.2mm, 7Ts"
  rect 4x4 hole 2.8: 1(-10.15,15.25) 1(-10.15,17.75)
  rrect50% 4x4 hole 2.8: 2(-10.15,-17.75) 2(-10.15,-15.25) 3(10.15,-17.75) 3(10.15,-15.25) 4(10.15,15.25) 4(10.15,17.75)
  silkscreen extent -13.5,-21 13.5,21, body extent -8.55,-10.45 8.45,9.55, height 26.52
ARCDC522747E152N2B [mm] "CM CHOKE 1.6mH, D2.2mm, 8Ts"
  rect 4x4 hole 2.8: 1(-10.15,15.25) 1(-10.15,17.75)
  rrect50% 4x4 hole 2.8: 2(-10.15,-17.75) 2(-10.15,-15.25) 3(10.15,-17.75) 3(10.15,-15.25) 4(10.15,15.25) 4(10.15,17.75)
  silkscreen extent -13.5,-26 13.5,26, body extent -8.55,-10.45 8.45,9.55, height 26.52
ARLDC472145C500N1B [mm] "DM CHOKE, 50uH, 9mohm"
  round 4 hole 2.5: 1(0,-9) 2(0,9)
  silkscreen extent -22.5,-10.5 22.5,10.5
ARLDC807842C201N1B [mm]
  round 5 hole 2.5: 1(-34.29,0) 2(5.08,0)
  silkscreen extent -37,-34 34,34
AUXP60W [mm]
  rect 1.5x1.5 hole 1: 1(32.029,0)
  round 1.5 hole 1: 2(32.029,-2.54) 3(34.569,0) 4(34.569,-2.54) 5(37.109,0) 6(37.109,-2.54) 7(-12.217,-1.27) 8(-9.677,-1.27) 9(-7.137,-1.27) 10(-2.54,-1.27) 11(0,-1.27)
  silkscreen extent -15.24,-3.81 42.79,3
B32924_21.5mm#1 [mm] "Epcos film capacitors, 27.5mm spacing"
  rect 2x2 hole 1.3: 1(-13.75,0)
  round 2 hole 1.5: 2(13.75,0)
  silkscreen extent -15.75,-6.25 15.75,6.25, body extent -15.75,-6.25 15.75,6.25, height 21.5
B32924_21.5mm#2 [mm] "Epcos film capacitors, 27.5mm spacing"
  rect 1.5x1.5 hole 1: 1(-13.75,0)
  round 1.5 hole 1: 2(13.75,0)
  silkscreen extent -15.75,-6.25 15.75,6.25, body extent -15.75,-6.25 15.75,6.25, height 21.5
B32924_21.5mm#3 [mm] "Epcos film capacitors, 27.5mm spacing"
  rect 2x2 hole 1.5: 1(-13.75,0)
  round 2 hole 1.5: 2(13.75,0)
  silkscreen extent -15.75,-6.25 15.75,6.25, body extent -15.75,-6.25 15.75,6.25, height 21.5
B32924_24.5mm [mm] "Epcos film capacitors, 27.5mm spacing"
  rect 1.5x1.5 hole 1: 1(-13.75,0)
  round 1.5 hole 1: 2(13.75,0)
  silkscreen extent -15.75,-7 15.75,7, body extent -15.75,-7 15.75,7, height 24.5
CD45_800x600x1200 [mm] "TH, 2-Leads, Dia 8mm, Pin Spacing 10 mm"
  round 1.4 hole 0.9: 1(-5,0) 2(5,0)
  silkscreen extent -3.99,-3 4.01,3, body extent -5.36,-3.01 5.36,3.01, height 12
CE_Mark_5mm [mm] "Minimum text height for CE Mark"
  silkscreen extent -3.5,-2.5 3.5,2.5
controlCARD-120HSEC [mm] "Pads are not numbered according to Samtec datasheet."
  rect 0.5x2.724 smd: 1(-23.357,-1.678) 2(-23.357,1.722) 3(-22.557,-1.678) 4(-22.557,1.722) 5(-21.757,-1.678) 6(-21.757,1.722) 7(-20.957,-1.678) 8(-20.957,1.722) 9(-20.157,-1.678) 10(-20.157,1.722) 11(-19.357,-1.678) 12(-19.357,1.722) 13(-18.557,-1.678) 14(-18.557,1.722) 15(-17.757,-1.678) 16(-17.757,1.722) 17(-16.957,-1.678) 18(-16.957,1.722) 19(-16.157,-1.678) 20(-16.157,1.722) 21(-15.357,-1.678) 22(-15.357,1.722) 23(-14.557,-1.678) 24(-14.557,1.722) 25(-13.757,-1.678) 26(-13.757,1.722) 27(-12.957,-1.678) 28(-12.957,1.722) 29(-12.157,-1.678) 30(-12.157,1.722) 31(-11.357,-1.678) 32(-11.357,1.722) 33(-10.557,-1.678) 34(-10.557,1.722) 35(-9.757,-1.678) 36(-9.757,1.722) 37(-8.957,-1.678) 38(-8.957,1.722) 39(-8.157,-1.678) 40(-8.157,1.722) 41(-7.357,-1.678) 42(-7.357,1.722) 43(-6.557,-1.678) 44(-6.557,1.722) 45(-5.757,-1.678) 46(-5.757,1.722) 47(-4.957,-1.678) 48(-4.957,1.722) 49(-4.157,-1.678) 50(-4.157,1.722) 51(-3.357,-1.678) 52(-3.357,1.722) 53(-2.557,-1.678) 54(-2.557,1.722) 55(-1.757,-1.678) 56(-1.757,1.722) 57(2.243,-1.678) 58(2.243,1.722) 59(3.043,-1.678) 60(3.043,1.722) 61(3.843,-1.678) 62(3.843,1.722) 63(4.643,-1.678) 64(4.643,1.722) 65(5.443,-1.678) 66(5.443,1.722) 67(6.243,-1.678) 68(6.243,1.722) 69(7.043,-1.678) 70(7.043,1.722) 71(7.843,-1.678) 72(7.843,1.722) 73(8.643,-1.678) 74(8.643,1.722) 75(9.443,-1.678) 76(9.443,1.722) 77(10.243,-1.678) 78(10.243,1.722) 79(11.043,-1.678) 80(11.043,1.722) 81(11.843,-1.678) 82(11.843,1.722) 83(12.643,-1.678) 84(12.643,1.722) 85(13.443,-1.678) 86(13.443,1.722) 87(14.243,-1.678) 88(14.243,1.722) 89(15.043,-1.678) 90(15.043,1.722) 91(15.843,-1.678) 92(15.843,1.722) 93(16.643,-1.678) 94(16.643,1.722) 95(17.443,-1.678) 96(17.443,1.722) 97(18.243,-1.678) 98(18.243,1.722) 99(19.043,-1.678) 100(19.043,1.722) 101(19.843,-1.678) 102(19.843,1.722) 103(20.643,-1.678) 104(20.643,1.722) 105(21.443,-1.678) 106(21.443,1.722) 107(22.243,-1.678) 108(22.243,1.722) 109(23.043,-1.678) 110(23.043,1.722) 111(23.843,-1.678) 112(23.843,1.722) 113(24.643,-1.678) 114(24.643,1.722) 115(25.443,-1.678) 116(25.443,1.722) 117(26.243,-1.678) 118(26.243,1.722) 119(27.043,-1.678) 120(27.043,1.722)
  round 0.025 hole 1.27 unplated mask+0.876: 181(-24.857,0.022) 182(28.543,1.522)
  round 1.348 hole 0.84: 185(-27.207,0.022) 186(30.893,0.022)
  silkscreen extent -32.11,-3.86 35.8,3.9, body extent -31.75,-3.48 35.3,3.52, height 12.35
D0008A_N [mm] "SOIC, 8-Leads, Body 4.9x3.9mm, Pitch 1.27mm, IPC Medium Density"
  oval 1.45x0.6 smd: 1(-2.725,1.905) 2(-2.725,0.635) 3(-2.725,-0.635) 4(-2.725,-1.905) 5(2.725,-1.905) 6(2.725,-0.635) 7(2.725,0.635) 8(2.725,1.905)
  silkscreen extent -3.3,-2.5 0.9,2.5, body extent -3,-2.45 3,2.45, height 1.63
D0016A_N [mm] "SOIC, 16-Leads, Body 9.9x3.9mm, Pitch 1.27mm, IPC Medium Density"
  oval 1.45x0.6 smd: 1(-2.725,4.445) 2(-2.725,3.175) 3(-2.725,1.905) 4(-2.725,0.635) 5(-2.725,-0.635) 6(-2.725,-1.905) 7(-2.725,-3.175) 8(-2.725,-4.445) 9(2.725,-4.445) 10(2.725,-3.175) 11(2.725,-1.905) 12(2.725,-0.635) 13(2.725,0.635) 14(2.725,1.905) 15(2.725,3.175) 16(2.725,4.445)
  silkscreen extent -3.3,-5 0.9,5, body extent -3,-4.95 3,4.95, height 1.6
DBV0005A_N [mm] "SOT23, 5-Leads, Body 2.9x1.6mm, Pitch 0.95mm, Lead Span 2.8mm, IPC Medium Density"
  rrect17% 1x0.6 smd: 1(-1.375,0.95) 2(-1.375,0) 3(-1.375,-0.95) 4(1.375,-0.95) 5(1.375,0.95)
  silkscreen extent -1.63,-1.55 0.38,1.55, body extent -1.42,-1.46 1.42,1.46, height 1.09
DBV0006A_N [mm] "SOT23, 6-Leads, Body 2.9x1.6mm, Pitch 0.95mm, Lead Span 2.8mm, IPC Medium Density"
  rrect17% 1x0.6 smd: 1(-1.375,0.95) 2(-1.375,0) 3(-1.375,-0.95) 4(1.375,-0.95) 5(1.375,0) 6(1.375,0.95)
  silkscreen extent -1.68,-1.55 0.5,1.55, body extent -1.42,-1.46 1.42,1.46, height 1.12
DBZ0003A_N [mm] "SOT23, 3-Leads, Body 2.9x1.3mm, Pitch 0.95mm, Lead Span 2.4mm, IPC Medium Density"
  rrect17% 1x0.6 smd: 1(-1.2,0.95) 2(-1.2,-0.95) 3(1.2,0)
  silkscreen extent 0.2,-1.5 0.7,1.5, body extent -1.26,-1.46 1.26,1.46, height 0.98
DVE0016A [mm] "SO-MOD-16"
  rrect17% 1.65x0.6 smd: 1(-4.875,4.445) 2(-4.875,3.175) 3(-4.875,1.905) 4(-4.875,0.635) 5(-4.875,-0.635) 6(-4.875,-1.905) 7(-4.875,-3.175) 8(-4.875,-4.445) 9(4.875,-4.445) 10(4.875,-3.175) 11(4.875,-1.905) 12(4.875,-0.635) 13(4.875,0.635) 14(4.875,1.905) 15(4.875,3.175) 16(4.875,4.445)
  body extent -5.17,-5.15 5.17,5.15, height 2.59
DW0016B_HV [mm] "SOIC-16, HV/isolation option"
  rrect17% 1.65x0.6 smd: 1(-4.875,4.445) 2(-4.875,3.175) 3(-4.875,1.905) 4(-4.875,0.635) 5(-4.875,-0.635) 6(-4.875,-1.905) 7(-4.875,-3.175) 8(-4.875,-4.445) 9(4.875,-4.445) 10(4.875,-3.175) 11(4.875,-1.905) 12(4.875,-0.635) 13(4.875,0.635) 14(4.875,1.905) 15(4.875,3.175) 16(4.875,4.445)
  silkscreen extent -3.5,-5.1 3.5,5.1, body extent -5.17,-5.15 5.17,5.15, height 2.59
DWY0006A [mm] "SOIC-6"
  rrect13% 1.905x0.76 smd: 1(-5.375,1.27) 2(-5.375,0) 3(-5.375,-1.27) 4(5.375,-1.27) 5(5.375,0) 6(5.375,1.27)
  silkscreen extent -3.45,-2.4 3.45,2.4, body extent -5.75,-2.4 5.75,2.4, height 3.31
FCC_disclaimer_stacked [mm]
Fiducial10-20 [mm]
  round 1 smd mask+0.5: 1(0,0)
  Top Layer keep-out circle w1.178: c0,0 r0.5
FP-IPT60R080G7XTMA1_HSOF-8-MFG [mm]
  rrect13% 0.8x2.5 smd paste-1000 mask+0: 1(-4.2,-5.35) 2(-3,-5.35)
  round 0.709 smd paste-1000 mask+0: 3-4-5-6-7-8(4.206,-4.881)
  round 7.2 smd paste-1000 mask+0: 9(0,2.7)
  Top Layer region: -4.85,-1.3 4.85,-1.3 4.85,2.4 4.35,2.4 4.35,5.2 5.05,5.2 5.05,6.7 -5.05,6.7 -5.05,5.2 -4.35,5.2 -4.35,2.4 -4.85,2.4
  Top Layer region: -2.2,-4.1 4.6,-4.1 4.6,-6.6 3.8,-6.6 3.8,-4.6 3.4,-4.6 3.4,-6.6 2.6,-6.6 2.6,-4.6 2.2,-4.6 2.2,-6.6 1.4,-6.6 1.4,-4.6 1,-4.6 1,-6.6 0.2,-6.6 0.2,-4.6 -0.2,-4.6 -0.2,-6.6 -1,-6.6 -1,-4.6 -1.4,-4.6 -1.4,-6.6 -2.2,-6.6 -2.2,-4.1
  body extent -4.95,-5.79 4.95,5.89, height 2.31
FP-KMB23STR_SMT_4MM725_3MM85-MFG [mm]
  rrect11% 1.84x0.9 smd paste+0 mask+0: 1(-3,1.2) 2(-3,-1.2) 3(3,-1.2) 4(3,1.2)
  silkscreen extent -4.62,-2.47 2.05,2.47, body extent -3.5,-2.36 3.5,2.36, height 3
FUSE_0325 [mm] "TH, 2-Leads, Dia 6.985mm, Pin Spacing 40.32mm"
  oval 2.5x3 hole 1.7: 1(-20.16,0) 2(20.16,0)
  silkscreen extent -18.95,-3.64 18.95,3.64, body extent -20.7,-3.64 20.7,3.64, height 7.26
HDR2X4 [mm] "Connector; Header; 4x2 Position"
  rect 1.5x1.5 hole 0.9: 1(0,0)
  round 1.5 hole 0.9: 2(0,2.54) 3(2.54,0) 4(2.54,2.54) 5(5.08,0) 6(5.08,2.54) 7(7.62,0) 8(7.62,2.54)
  silkscreen extent -1.27,-1.27 8.89,3.81
IEC_HighVoltage_Small [mm]
  silkscreen extent -2.72,-2.24 2.72,2.47
IEC_HotSurface_Small [mm]
  silkscreen extent -2.72,-2.36 2.72,2.35
Keystone5000#1 [mm] "For Keystone 500x miniature loop terminals"
  round 6 hole 3: 1(0,0)
  silkscreen extent -1.33,-1.33 1.33,1.33, body extent -1.24,-1.24 1.25,1.25, height 4.62
Keystone5000#2 [mm] "For Keystone 500x miniature loop terminals"
  round 2.032 hole 1.016: 1(0,0)
  silkscreen extent -1.33,-1.33 1.33,1.33, body extent -1.24,-1.24 1.25,1.25, height 4.62
Keystone5001 [mm] "For Keystone 500x miniature loop terminals"
  round 6 hole 3: 1(0,0)
  silkscreen extent -1.33,-1.33 1.33,1.33, body extent -1.24,-1.24 1.25,1.25, height 4.62
Keystone5004 [mil] "For Keystone 500x miniature loop terminals"
  round 80 hole 40: 1(0,0)
  silkscreen extent -52,-52 52,52, body extent -49,-49 49,49, height 182
Keystone_1902C [mil] "Hex Standoff, 4-40 threaded, nylon"
  round 1 on Mech4: 0(0,0)
  body extent -145,-126 146,126, height 501
KY_700x500x1000 [mm] "TH, 2- Leads, Body 7x5mm, Pin Spacing 7.5mm"
  round 1.4 hole 0.9: 1(-3.75,0) 2(3.75,0)
  silkscreen extent -3.5,-2.5 3.5,2.5, body extent -4.05,-2.5 4.05,2.5, height 9.97
Label_650x200 [mil] "Thermal Transfer Label"
  round 1 on Mech13: 0(0,0)
  silkscreen extent -325,-100 325,100, body extent -325,-100 325,100, height 1
Mill-Max_0312-0-15-15-34-27-10-0 [mm] "Pin Receptacle, .032-.046\" .075\" Dia, Gold, TH"
  round 2.45 hole 1.905: 1(0,0)
  silkscreen extent -1.52,-1.52 1.52,1.52, body extent -1.15,-1.15 1.16,1.15, height 0.46
Molex_0448120024 [mm] "Receptacle, 2.54mm, 6x1, TH"
  round 1.55 hole 1.02: 1(-6.35,-1.905) 2(-3.81,-1.905) 2(-3.81,1.905) 3(-1.27,-1.905) 3(-1.27,1.905) 4(1.27,-1.905) 4(1.27,1.905) 5(3.81,-1.905) 5(3.81,1.905) 6(6.35,-1.905) 6(6.35,1.905)
  rect 1.55x1.55 hole 1.02: 1(-6.35,1.905)
  silkscreen extent -8.2,-4.09 8.08,3.4, body extent -7.92,-4.09 8.08,3.4, height 4.5
MS2250004 [mm] "INRSH CURR LIMITER 50 OHM 25% 4A 23MM"
  round 2 hole 1.2: 1(3.35,-3.4) 2(-3.35,3.4)
  silkscreen extent -11.5,-5 11.5,5, body extent -11.81,-3.81 11.81,3.81, height 27.3
"NY PMS 440 0025 PH" [mm] "4-40 nylon screw and mounting hole"
  round 0 hole 3.2 unplated: 1(0,0)
  body extent -3.3,-3.3 3.3,3.3, height 2.69
PK0003A_M [mm] "SOT89, 3-Leads, Body 4.5x2.5mm, Pitch 1.5mm, IPC Low Density"
  rrect14% 1.6x0.7 smd: 1(-0.025,1.5) 3(-0.025,-1.5)
  rrect14% 1.7x0.7 smd: 2(0.025,0)
  Top Layer region: 0.875,0.35 1.525,1 3.925,1 4.575,0.35 4.575,-0.35 3.925,-1 1.525,-1 0.875,-0.35 0.675,-0.35 0.675,0.35
  silkscreen extent -0.62,-2.3 3.53,2.3, body extent -0.26,-2.25 3.84,2.25, height 1.6
SOD-123 [mm] "On Semi recommended land pattern"
  rect 0.915x1.22 smd: 1(-1.637,0) 2(1.637,0)
  silkscreen extent -2.74,-1.17 2.03,1.17, body extent -1.93,-0.9 1.93,0.9, height 1.35
sod-323 [mm] "NXP recommended land pattern"
  rect 0.6x0.6 smd paste-0.05: 1(-1.1,0) 2(1.1,0)
  silkscreen extent -2.06,-0.86 1.53,0.86, body extent -1.3,-0.67 1.3,0.68, height 1.1
TDK_ACM2520-2P [mm] "SMD, 4-Leads, Body 2.5x2mm"
  rect 0.8x0.4 smd: 1(-1.15,0.65) 2(-1.15,-0.65) 3(1.15,-0.65) 4(1.15,0.65)
  silkscreen extent -1.45,-1.2 1.45,1.4, body extent -1.35,-1.1 1.35,1.1, height 1.3
TI_Stacked_Overlay_Small [mm]
  silkscreen extent -10.63,-2.49 10.63,2.49
VAR_S10K275E2 [mm] "EPCOS"
  round 1.6 hole 1.1: 1(-3.75,1.1) 2(3.75,-1.1)
  silkscreen extent -6,-2.7 6,2.7, body extent -5.98,-2.7 5.98,2.7, height 14.99
VLS252010HBX [mm] "TDK"
  rect 0.6x2 smd: 1(-0.95,0) 2(0.95,0)
  silkscreen extent -0.25,-1.1 0.25,1.1, body extent -1.35,-1.1 1.35,1.1, height 1
"WCAP-AI3H_3500x5700 - H" [mm]
  rrect50% 3x3 hole 2: 1(-5,0)
  round 3 hole 2: 2(5,0)
  silkscreen extent -17.5,-17.5 17.5,17.5, body extent -17.46,-17.5 17.5,17.5, height 56.82
WEEE_Minimum [mm] "WEEElie bin"
  silkscreen extent -2.42,-4.38 2.52,2.65
Wurth_750315371 [mm] "SMD, Body 12.6x8.3mm, Pitch 2.54mm"
  rect 1.83x1.09 smd: 1(-5.62,2.54) 2(-5.62,0) 3(-5.62,-2.54) 4(5.62,-2.54) 5(5.62,0) 6(5.62,2.54)
  silkscreen extent -6.3,-4.15 6.3,4.4, body extent -6.35,-4.2 6.35,4.2, height 4.11
? [mil] "LMG3425R030 Daughter Card"
  rrect10% 70x70 hole 40.16: 1(0,-70)
  round 70 hole 40.16: 2(0,30) 3(100,-70) 4(100,30) 5(200,-70) 6(200,30) 7(300,-70) 8(300,30) 9(400,-70) 10(400,30) 11(500,-70) 12(500,30)
  round 96.46 hole 75: 20(-1800,102) 21(-1600,102) 22(-1300,100) 23(-1100,100) 24(-800,100) 25(-600,100)
  silkscreen extent -2236,-120 776,162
